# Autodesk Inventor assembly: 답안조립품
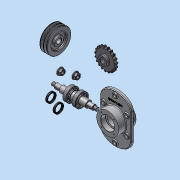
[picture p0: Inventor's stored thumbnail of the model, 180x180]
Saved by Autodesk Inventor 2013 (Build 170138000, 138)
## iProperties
Created: 2015-02
Part Number: 답안조립품
Document SubType Name: Assembly
Designer: dgall
Author: dgall
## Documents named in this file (11)
- C:\Users\dgall\Desktop\450207V1027\답안조립품.iam
- C:\Users\dgall\Desktop\450207V1027\1-본체.ipt
- C:\Users\dgall\Desktop\450207V1027\2-커버.ipt
- C:\Users\dgall\Desktop\450207V1027\3-축.ipt
- C:\Users\dgall\Desktop\450207V1027\4-V벨트풀리.ipt
- C:\Users\dgall\Desktop\450207V1027\5-체인 스프로킷.ipt
- C:\Users\dgall\Desktop\450207V1027\6-베어링 6206.ipt
- C:\Users\dgall\Desktop\450207V1027\7-부시.ipt
- C:\Users\dgall\Desktop\450207V1027\8-오일실 30x42.ipt
- C:\Users\dgall\Desktop\450207V1027\9-M16-너트.ipt
- C:\Users\dgall\Desktop\450207V1027\11-키 6x6.ipt
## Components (15 placed, 10 different names)
1. 1-본체:1
2. 2-커버:1
3. 2-커버:2
4. 3-축:1
5. 4-V벨트풀리:1
6. 5-체인 스프로킷:1
7. 6-베어링 6206:1
8. 6-베어링 6206:2
9. 7-부시:1
10. 8-8-오일실 30x42:1
11. 8-8-오일실 30x42:2
12. 9-M16 너트:1
13. 9-M16 너트:2
14. 11-키 6x6:1
15. 11-키 6x6:2
